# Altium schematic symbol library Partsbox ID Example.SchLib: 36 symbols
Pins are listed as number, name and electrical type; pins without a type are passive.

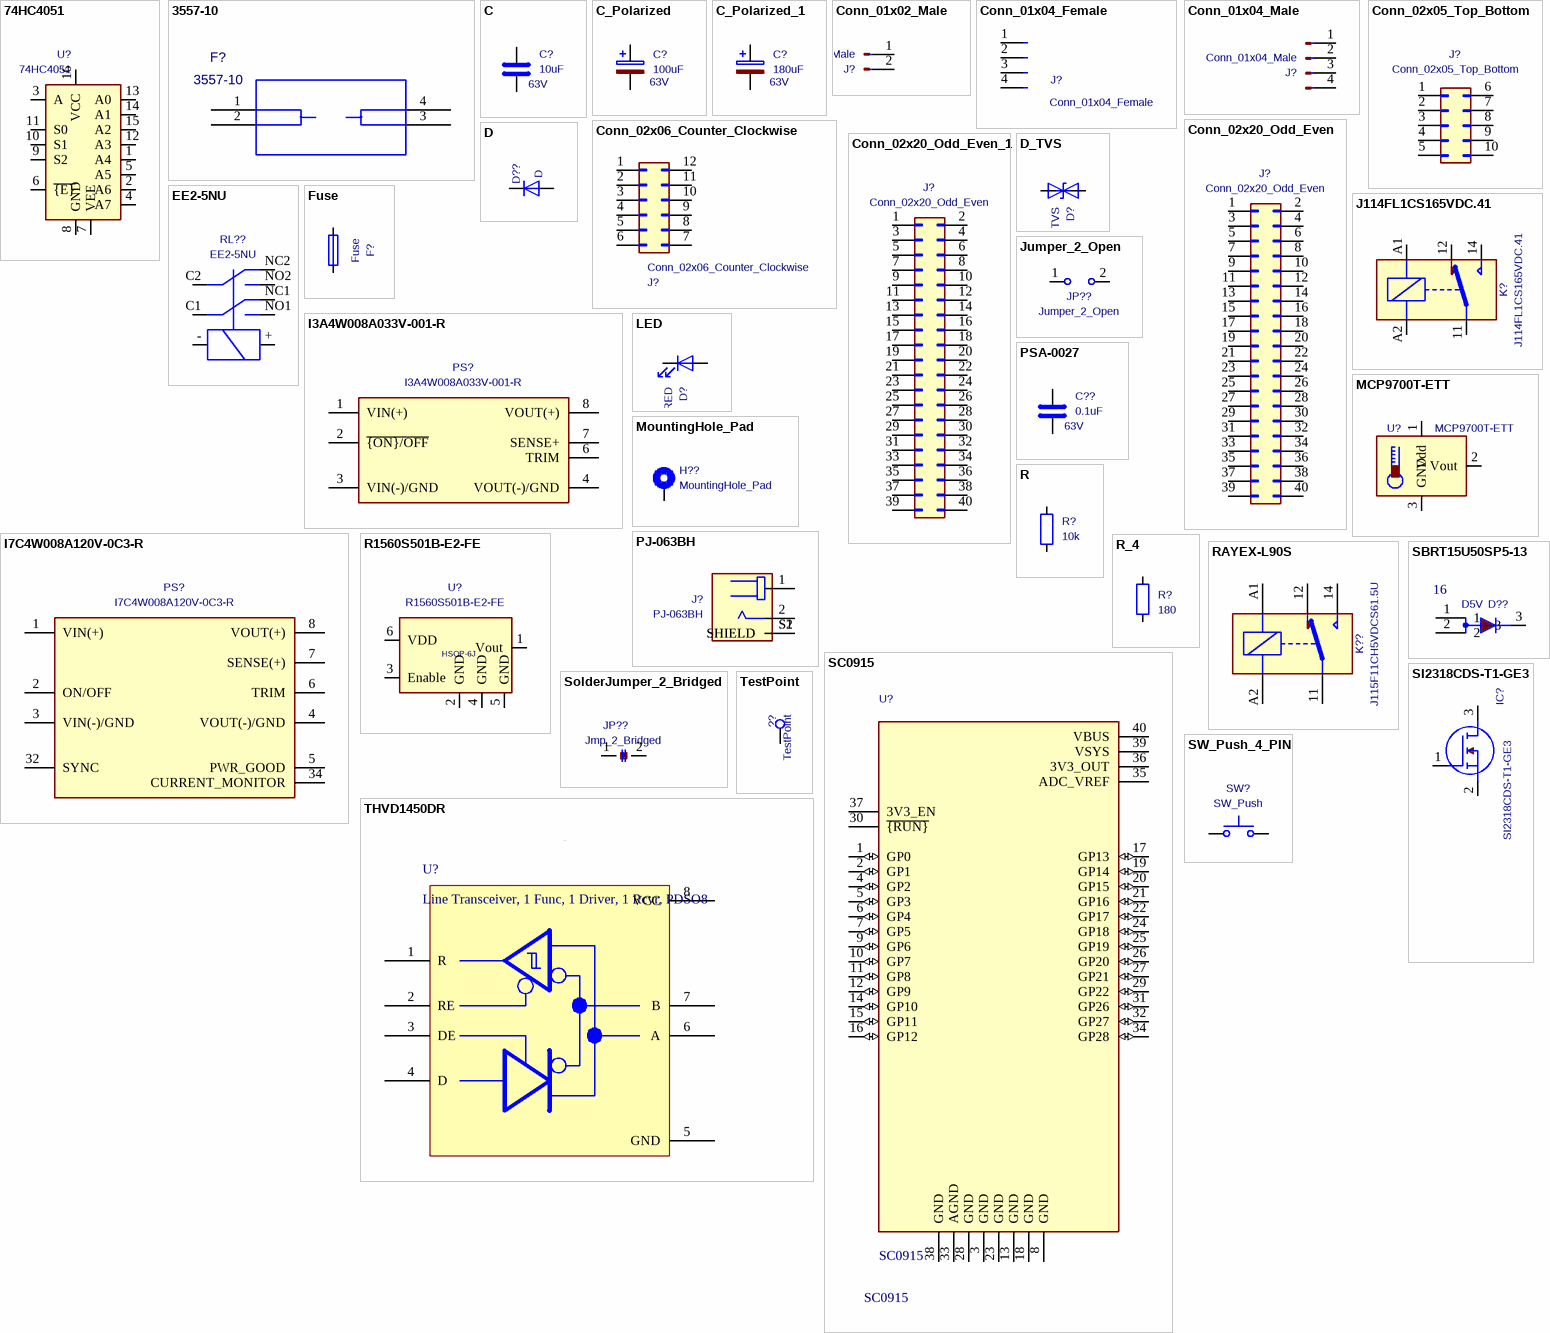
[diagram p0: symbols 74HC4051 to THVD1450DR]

## 74HC4051
designator U?
Single-Ended Multiplexer, 1 Func, 8 Channel, CMOS, PDSO16; Manufacturer: Nexperia; Manufacturer Part Number: 74HC4051PW,118; Package Body Material: Plastic; Number of Channels: 8; Channels: 1; Off-state Isolation-Nom: 50dB; On-state Resistance Match-Nom: 9R; On-state Resistance-Max (Ron): 180R; Max Supply Voltage: 10V; Min Supply Voltage: 2V; Nominal Supply Voltage: 5V; Switch-off Time-Max: 87ns; Switch-on Time-Max: 104ns
footprint TSSOP-16_4.4x5mm_P0.65mm
pins: 1 A4, 2 A6, 3 A, 4 A7, 5 A5, 6 ~{{E}}, 7 VEE, 8 GND, 9 S2, 10 S1, 11 S0, 12 A3, 13 A0, 14 A1, 15 A2, 16 VCC

## 3557-10
designator F?
Holder; Fuse; Auto Blade; 30A; PC Pin Terminal; Nylon Holder; Red; Manufacturer: Keystone Electronics
footprint 3557-10
pins: 1, 2, 3, 4

## C
designator C?  value 10uF  Voltage: 63V  (hidden comment: C)
Ceramic Capacitor, Multilayer, Ceramic, 63V, 10% +Tol, 10% -Tol, X7R, 15% TC, 10uF, Surface Mount, 1210; Manufacturer: Samsung; Manufacturer Part Number: CL32B106KMVNNWE; Multilayer: Yes
footprint C_1210_3225Metric
pins: 1, 2

## C_Polarized
designator C?  value 100uF  Voltage: 63V  (hidden comment: C_Polarized)
Aluminum Electrolytic Capacitor, Polarized, 63V, 20% +Tol, 20% -Tol, 100uF, Surface Mount, 4141; Manufacturer: KEMET; Manufacturer Part Number: A768MS107M1JLAE027
footprint CP_Elec_10x12.6
pins: 1, 2

## C_Polarized_1
designator C?, comment value 180uF  Voltage: 63V  (hidden comment: Comment)
Cap Alu Hybrid SMD 150C 63V 180F; Manufacturer: KEMET; Manufacturer Part Number: A785MW187M1JLAS013
footprint CP_Elec_10x12.6
pins: 1, 2

## Conn_01x02_Male
designator J?
Barrier Strip Terminal Block, 8A, 1 Row(s), 1 Deck(s); Manufacturer: Phoenix Contact; Manufacturer Part Number: 1843606; Fastening Method: CONNECTOR; Number of Decks: 1; Number of Ways: 2; Voltage Rating: 160V; Safety Approval: UL
footprint 1843606
pins: 1 Pin_1, 2 Pin_2

## Conn_01x04_Female
designator J?
Board Connector, 4 Contact(s), 1 Row(s), Female, Straight, 0.1 inch Pitch, Solder Terminal, Locking; Manufacturer: Sullins; Manufacturer Part Number: PPPC041LFBN-RC; Manufacturer Series: PP; Contact Pattern: RECTANGULAR; Contact Style: SQ PIN-SKT; Number Of Connectors: 1; Polarization Key: POLARIZED HOUSING; Rated Current (Signal): 3A; Number of Contacts: 4; Body Breadth: 0.094inch; Body Depth: 0.334inch; Body Length: 0.42inch; Reference Standard: UL; Reliability: COMMERCIAL
footprint PinHeader_1x04_P2.54mm_Vertical
pins: 1 Pin_1, 2 Pin_2, 3 Pin_3, 4 Pin_4

## Conn_01x04_Male
designator J?
Strip Terminal Block, 16A, 1 Row(s), 1 Deck(s); Manufacturer: Phoenix Contact; Manufacturer Part Number: 1924321; Fastening Method: CONNECTOR; Number of Decks: 1; Number of Ways: 4; Voltage Rating: 320V; Safety Approval: UL,VDE,CUL,CB,EAC
footprint 1924321
pins: 1 Pin_1, 2 Pin_2, 3 Pin_3, 4 Pin_4

## Conn_02x05_Top_Bottom
designator J?
Board Connector, 10 Contact(s), 2 Row(s), Female, Straight, 0.1 inch Pitch, Solder Terminal, Locking; Manufacturer: Sullins; Manufacturer Part Number: PPPC052LFBN-RC; Manufacturer Series: PP; Option: General Purpose; Contact Pattern: RECTANGULAR; Contact Style: SQ PIN-SKT; Filter Feature: No; Number Of Connectors: 1; Number Of PCB Rows: 2; Polarization Key: POLARIZED HOUSING; Rated Current (Signal): 3A; Number of Contacts: 10; Body Breadth: 0.197inch; Body Depth: 0.334inch; Body Length: 0.52inch; PCB Contact Row Spacing: 2.54mm; Reference Standard: UL; Reliability: COMMERCIAL
footprint PinSocket_2x05_P2.54mm_Vertical
pins: 1 Pin_1, 2 Pin_2, 3 Pin_3, 4 Pin_4, 5 Pin_5, 6 Pin_6, 7 Pin_7, 8 Pin_8, 9 Pin_9, 10 Pin_10

## Conn_02x06_Counter_Clockwise
designator J?
Board Connector, 12 Contact(s), 2 Row(s), Female, Straight, 0.1 inch Pitch, Solder Terminal, Locking; Manufacturer: Sullins; Manufacturer Part Number: PPPC062LFBN-RC; Manufacturer Series: PP; Contact Pattern: RECTANGULAR; Contact Style: SQ PIN-SKT; Number Of Connectors: 1; Number Of PCB Rows: 2; Polarization Key: POLARIZED HOUSING; Rated Current (Signal): 3A; Number of Contacts: 12; Body Breadth: 0.197inch; Body Depth: 0.334inch; Body Length: 0.62inch; PCB Contact Row Spacing: 2.54mm; Reference Standard: UL; Reliability: COMMERCIAL
footprint PinHeader_2x06_P2.54mm_Vertical
pins: 1 Pin_1, 2 Pin_2, 3 Pin_3, 4 Pin_4, 5 Pin_5, 6 Pin_6, 7 Pin_7, 8 Pin_8, 9 Pin_9, 10 Pin_10, 11 Pin_11, 12 Pin_12

## Conn_02x20_Odd_Even
designator J?
Board Connector; Manufacturer: Omron; Manufacturer Part Number: XG4A-4035; Manufacturer Series: XG4A
footprint PinHeader_2x20_P2.54mm_Horizontal
pins: 1 Pin_1, 2 Pin_2, 3 Pin_3, 4 Pin_4, 5 Pin_5, 6 Pin_6, 7 Pin_7, 8 Pin_8, 9 Pin_9, 10 Pin_10, 11 Pin_11, 12 Pin_12, 13 Pin_13, 14 Pin_14, 15 Pin_15, 16 Pin_16, 17 Pin_17, 18 Pin_18, 19 Pin_19, 20 Pin_20, 21 Pin_21, 22 Pin_22, 23 Pin_23, 24 Pin_24, 25 Pin_25, 26 Pin_26, 27 Pin_27, 28 Pin_28, 29 Pin_29, 30 Pin_30, 31 Pin_31, 32 Pin_32, 33 Pin_33, 34 Pin_34, 35 Pin_35, 36 Pin_36, 37 Pin_37, 38 Pin_38, 39 Pin_39, 40 Pin_40

## Conn_02x20_Odd_Even_1
designator J?, comment Conn_02x20_Odd_Even
Board Connector, 40 Contact(s), 2 Row(s), Female, Straight, 0.1 inch Pitch, Solder Terminal, Locking; Manufacturer: Sullins; Manufacturer Part Number: PPPC202LFBN-RC; Manufacturer Series: PP; Contact Pattern: RECTANGULAR; Contact Style: SQ PIN-SKT; Number Of Connectors: 1; Number Of PCB Rows: 2; Polarization Key: POLARIZED HOUSING; Rated Current (Signal): 3A; Number of Contacts: 40; Body Breadth: 0.197inch; Body Depth: 0.334inch; Body Length: 2.02inch; PCB Contact Row Spacing: 2.54mm; Reference Standard: UL; Reliability: COMMERCIAL
footprint PinHeader_2x20_P2.54mm_Vertical
pins: 1 Pin_1, 2 Pin_2, 3 Pin_3, 4 Pin_4, 5 Pin_5, 6 Pin_6, 7 Pin_7, 8 Pin_8, 9 Pin_9, 10 Pin_10, 11 Pin_11, 12 Pin_12, 13 Pin_13, 14 Pin_14, 15 Pin_15, 16 Pin_16, 17 Pin_17, 18 Pin_18, 19 Pin_19, 20 Pin_20, 21 Pin_21, 22 Pin_22, 23 Pin_23, 24 Pin_24, 25 Pin_25, 26 Pin_26, 27 Pin_27, 28 Pin_28, 29 Pin_29, 30 Pin_30, 31 Pin_31, 32 Pin_32, 33 Pin_33, 34 Pin_34, 35 Pin_35, 36 Pin_36, 37 Pin_37, 38 Pin_38, 39 Pin_39, 40 Pin_40

## D
designator D??, comment value D  (hidden comment: Comment)
Rectifier Diode, Schottky, 1 Phase, 1 Element, 1A, 40V V(RRM), Silicon; Manufacturer: MCC; Manufacturer Part Number: SM5819PL-TP; Package Body Material: Plastic; Non-rep Pk Forward Current-Max: 30A; Number of Elements: 1; Max Power Dissipation: 1.14W; Time @ Peak Reflow Temperature-Max (s): 10s; Qualification Status: Not Qualified
footprint D_SOD-123F
pins: 1 K, 2 A

## D_TVS
designator D?
Trans Voltage Suppressor Diode, 400W, 51V V(RWM), Bidirectional, 1 Element, Silicon, DO-214AC; Manufacturer: Littelfuse; Manufacturer Part Number: SMAJ51CA; Package Body Material: Plastic; Max Breakdown Voltage: 62.7V; Min Breakdown Voltage: 56.7V; Breakdown Voltage-Nom: 59.7V; Clamping Voltage-Max: 82.4V; Number of Elements: 1; Time @ Peak Reflow Temperature-Max (s): 40s; Qualification Status: Not Qualified
footprint D_SMA
pins: 1 A1, 2 A2

## EE2-5NU
designator RL??, comment value EE2-5NU  (hidden comment: Comment)
Power/Signal Relay; Manufacturer: KEMET; Manufacturer Part Number: EE2-5NU-L
footprint EE2-5NU
pins: +, -, C1, C2, NC1, NC2, NO1, NO2

## Fuse
designator F?
Fuse Chip Medium Time Delay Acting 25A 250V SMD Solder Pad 3912 9.8 X 3.05 X 4.06mm Ceramic; Manufacturer: Bel; Manufacturer Part Number: 0678L9250-02; Fuse Type: Board Mount (Cartridge Style Excluded); Voltage Rating (DC): 72V; DC Cold Resistance: 1.9mR
footprint FUSC9830X318N
pins: 1, 2

## I3A4W008A033V-001-R
designator PS?
DC-DC Regulated Power Supply Module, 1 Output, 100W, Hybrid; MANUFACTURER: TDK-Lambda
footprint CONV_I3A4W008A033V-001-R
pins: 1 VIN(+), 2 ~{{ON}/OFF}, 3 VIN(-)/GND, 4 VOUT(-)/GND, 6 TRIM, 7 SENSE+, 8 VOUT(+)

## I7C4W008A120V-0C3-R
designator PS?
Power Supply Module; MANUFACTURER: TDK; SNAPEDA_PN: i7C4W012A050V-0C3-R
footprint CONV_I7C4W008A120V-0C3-R
pins: 1 VIN(+), 2 ON/OFF, 3 VIN(-)/GND, 4 VOUT(-)/GND, 5 PWR_GOOD, 6 TRIM, 7 SENSE(+), 8 VOUT(+), 32 SYNC, 34 CURRENT_MONITOR

## J114FL1CS165VDC.41
designator K?
Relay Ul Approved Gen Purpose Sp; Manufacturer: CIT Relay & Switch
footprint Big Pads - Relay_SPDT_Schrack-RT1-16A-FormC_RM5mm
pins: 11, 12, 14, A1, A2

## Jumper_2_Open
designator JP??, comment value Jumper_2_Open  (hidden comment: Comment)
footprint PinHeader_1x02_P2.54mm_Vertical
pins: 1 A, 2 B

## LED
designator D?  value RED  (hidden comment: LED)
Single Color LED, Red, Water Clear, 2.06mm; Manufacturer: Vishay Lite-On; Manufacturer Part Number: LTST-C150KRKT; Shape: Rectangular; Forward Current: 30mA; Forward Voltage: 2.4V; Luminous Intensity-Min: 130cd; Luminous Intensity-Nom: 54mcd; Channels: 1; Reverse Voltage-Max: 5V; Viewing Angle: 130°; Overall Height: 1.1mm
footprint LED_1206_3216Metric
pins: 1 K, 2 A

## MCP9700T-ETT
designator U?
Analog Voltage Output Sensor, 12 Bit(s), 6Cel, Rectangular, 3 Pin, Surface Mount; Manufacturer: Microchip; Manufacturer Part Number: MCP9700T-E/TT; Package Body Material: Plastic; Accuracy-Max (Cel): 4°C; Linearity (Cel): 0.5°C; Operating Current-Max: 12uA; Package Equivalence Code: TO-236; Power Supplies: 2.5/5V; Sensor Type: TEMPERATURE SENSOR,ANALOG,VOLTAGE OUTPUT; Max Supply Voltage: 5.5V; Min Supply Voltage: 2.3V; Body Breadth: 1.3mm; Body Height: 1.01mm; Body Length or Diameter: 2.9mm
footprint SOT-23
pins: 1 Vdd, 2 Vout, 3 GND

## MountingHole_Pad
designator H??, comment value MountingHole_Pad  (hidden comment: Comment)
footprint MountingHole_3.2mm_M3_DIN965_Pad
pins: 1

## PJ-063BH
designator J?
Circular DC Power Connector, 24V, 8A, 2.5mm Dia; MANUFACTURER: CUI INC
footprint CUI_PJ-063BH
pins: 1, 2, S1 SHIELD, S2 SHIELD

## PSA-0027
designator C??, comment value 0.1uF  Voltage: 63V  (hidden comment: Comment)
Ceramic Capacitor, Multilayer, Ceramic, 100V, 10% +Tol, 10% -Tol, X7R, 15% TC, 0.1uF, Surface Mount, 1206; Manufacturer: KEMET; Manufacturer Part Number: C1206C104K1RACAUTO; Multilayer: Yes; Reference Standard: AEC-Q200
footprint C_1206_3216Metric
pins: 1, 2

## R
designator R?  value 10k  (hidden comment: R)
Fixed Resistor, Thin Film, 0.25W, 10000ohm, 200V, 1% +/-Tol, 50ppm/Cel, Surface Mount, 1206; Manufacturer: Yageo; Manufacturer Part Number: RT1206FRE0710KL; Additional Feature: HIGH PRECISION; Rated Temperature: 70°C; Temperature Coefficient (ppm/Cel): 50; Package Height: 0.55mm; Package Length: 3.1mm; Package Width: 1.6mm; Power: 250mW
footprint R_1206_3216Metric
pins: 1, 2

## R1560S501B-E2-FE
designator U?
Standard Regulator Pos 5V 0.1A Automotive 6-Pin HSOP-J; Manufacturer: Ricoh
footprint HSOP-6J
pins: 1 Vout, 2 GND, 3 Enable, 4 GND, 5 GND, 6 VDD

## R_4
designator R?  value 180  (hidden comment: R_4)
Fixed Resistor, Metal Glaze/thick Film, 4W, 180ohm, 250V, 5% +/-Tol, 100ppm/Cel, Surface Mount, 2817; Manufacturer: TE Connectivity; Manufacturer Part Number: 3540180RJT
footprint RES_3540_TEC
pins: 1, 2

## RAYEX-L90S
designator K??, comment value J115F11CH5VDCS61.5U  (hidden comment: Comment)
50 Amp Relay Ul Approved Heavy Du; Manufacturer: CIT Relay & Switch
footprint Relay_SPDT_RAYEX-L90S
pins: 11, 12, 14, A1, A2

## SBRT15U50SP5-13
designator D??, comment value D5V  Pins: 16  (hidden comment: Comment)
Single-Ended Multiplexer, 1 Func, 8 Channel, CMOS, PDSO16; Manufacturer: Nexperia; Manufacturer Part Number: 74HC4051PW,118; Package Body Material: Plastic; Number of Channels: 8; Channels: 1; Off-state Isolation-Nom: 50dB; On-state Resistance Match-Nom: 9R; On-state Resistance-Max (Ron): 180R; Max Supply Voltage: 10V; Min Supply Voltage: 2V; Nominal Supply Voltage: 5V; Switch-off Time-Max: 87ns; Switch-on Time-Max: 104ns
footprint POWERDI5_DIO
pins: 1, 2, 3

## SC0915
designator U?
Raspberry Pi Pico Embedded Dev Module ¦ Raspberry Pi SC0915
footprint MODULE_SCO915_Custom_HeaderStyle
pins: 1 GP0 (io), 2 GP1 (io), 3 GND, 4 GP2 (io), 5 GP3 (io), 6 GP4 (io), 7 GP5 (io), 8 GND, 9 GP6 (io), 10 GP7 (io), 11 GP8 (io), 12 GP9 (io), 13 GND, 14 GP10 (io), 15 GP11 (io), 16 GP12 (io), 17 GP13 (io), 18 GND, 19 GP14 (io), 20 GP15 (io), 21 GP16 (io), 22 GP17 (io), 23 GND, 24 GP18 (io), 25 GP19 (io), 26 GP20 (io), 27 GP21 (io), 28 GND, 29 GP22 (io), 30 ~{{RUN}}, 31 GP26 (io), 32 GP27 (io), 33 AGND, 34 GP28 (io), 35 ADC_VREF, 36 3V3_OUT, 37 3V3_EN, 38 GND, 39 VSYS, 40 VBUS

## SI2318CDS-T1-GE3
designator IC?
Small Signal Field-Effect Transistor, 5.6A I(D), 40V, 1-Element, N-Channel, Silicon, Metal-oxide Semiconductor FET, TO-236AB; MANUFACTURER_NAME: Vishay; Manufacturer: Vishay Siliconix; Package Body Material: Plastic; Drain-source On Resistance-Max: 42mR; Number of Elements: 1; Operating Mode: ENHANCEMENT MODE; Power Dissipation-Max (Abs): 2.1W; Time @ Peak Reflow Temperature-Max (s): 30s; Transistor Application: SWITCHING; Qualification Status: Not Qualified
footprint SOT95P237X112-3N
pins: 1, 2, 3

## SolderJumper_2_Bridged
designator JP??, comment value Jmp_2_Bridged  (hidden comment: Comment)
footprint SolderJumper-2_P1.3mm_Bridged_Pad1.0x1.5mm
pins: 1 A, 2 B

## SW_Push_4_PIN
designator SW?  value SW_Push  (hidden comment: SW_Push_4_PIN)
Keypad Switch, 1 Switches, SPST, Momentary, 0.05A, 12VDC, 3.04N, Solder Terminal, Surface Mount-straight; Manufacturer: E-Switch; Manufacturer Part Number: TL3305BF260QG; Circuit Configuration: 1X1; Contact Current(DC)-Max: 50mA; Contact DC Max Rating R Load: .05A@12VDC; Contact Voltage(DC)-Max: 12V; Number of Switches: 1; Body Breadth: 4.5mm; Body Height: 4.9mm
footprint SW_TL3305BF260QG
pins: 1, 2

## TestPoint
designator ??, comment value TestPoint  (hidden comment: Comment)
footprint TestPoint_Pad_D1.0mm
pins: 1

## THVD1450DR
designator U?, comment Line Transceiver, 1 Func, 1 Driver, 1 Rcvr, PDSO8
Manufacturer: Texas Instruments; Manufacturer Part Number: THVD1450DR; Package Body Material: Plastic; Differential Output: Yes; Driver Number of Bits: 1; Input Characteristics: DIFFERENTIAL SCHMITT TRIGGER; Receive Delay-Max: 40ns; Max Supply Voltage: 5.5V; Min Supply Voltage: 3V; Nominal Supply Voltage: 5V; Transmit Delay-Max: 20ns
pins: 1 R, 2 RE, 3 DE, 4 D, 5 GND, 6 A, 7 B, 8 VCC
